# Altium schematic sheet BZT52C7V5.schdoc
size 127 x 101 mm
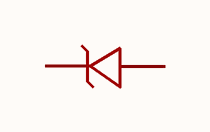
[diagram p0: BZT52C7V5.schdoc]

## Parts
D?  bzt52c7v5_c2121  [SOD-123_L2.7-W1.6-LS3.7-RD-1]  (value not drawn)

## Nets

Not connected (* = marked no-connect by the designer): D? 1(C) 2(A)

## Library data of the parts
D? = bzt52c7v5_c2121: 二极管配置:1个独立式;稳压值(标称值):7.5V;稳压值(范围):7V~7.9V;耗散功率(Pd):500mW;; Manufacturer: CJ(江苏长电/长晶); AddInBom: yes; ModelId: 528459655f7d4601a76356f3191c812b; ModelTransform: 151.575,66.929,0,0,0,0,0,0,0; Diode Configuration: 1个独立式; Zener Voltage(Nom): 7.5V; Reverse Leakage Current (Ir): 1uA; Pd - Power Dissipation: 500mW; Impedance(Zzt): 15Ω; Impedance(Zzk): 80Ω; Operating Junction Temperature Range: -55℃~+150℃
